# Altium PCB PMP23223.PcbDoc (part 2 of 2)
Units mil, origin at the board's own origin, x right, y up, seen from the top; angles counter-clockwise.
Board outline 2732.07 x 1574.8 mil, 4 copper layers (Top Layer 1, GND plane, Bottom Layer, Bottom Layer 1), stack 70.356 mil thick; 100 components, 33 nets, 239 pads, 115 vias.
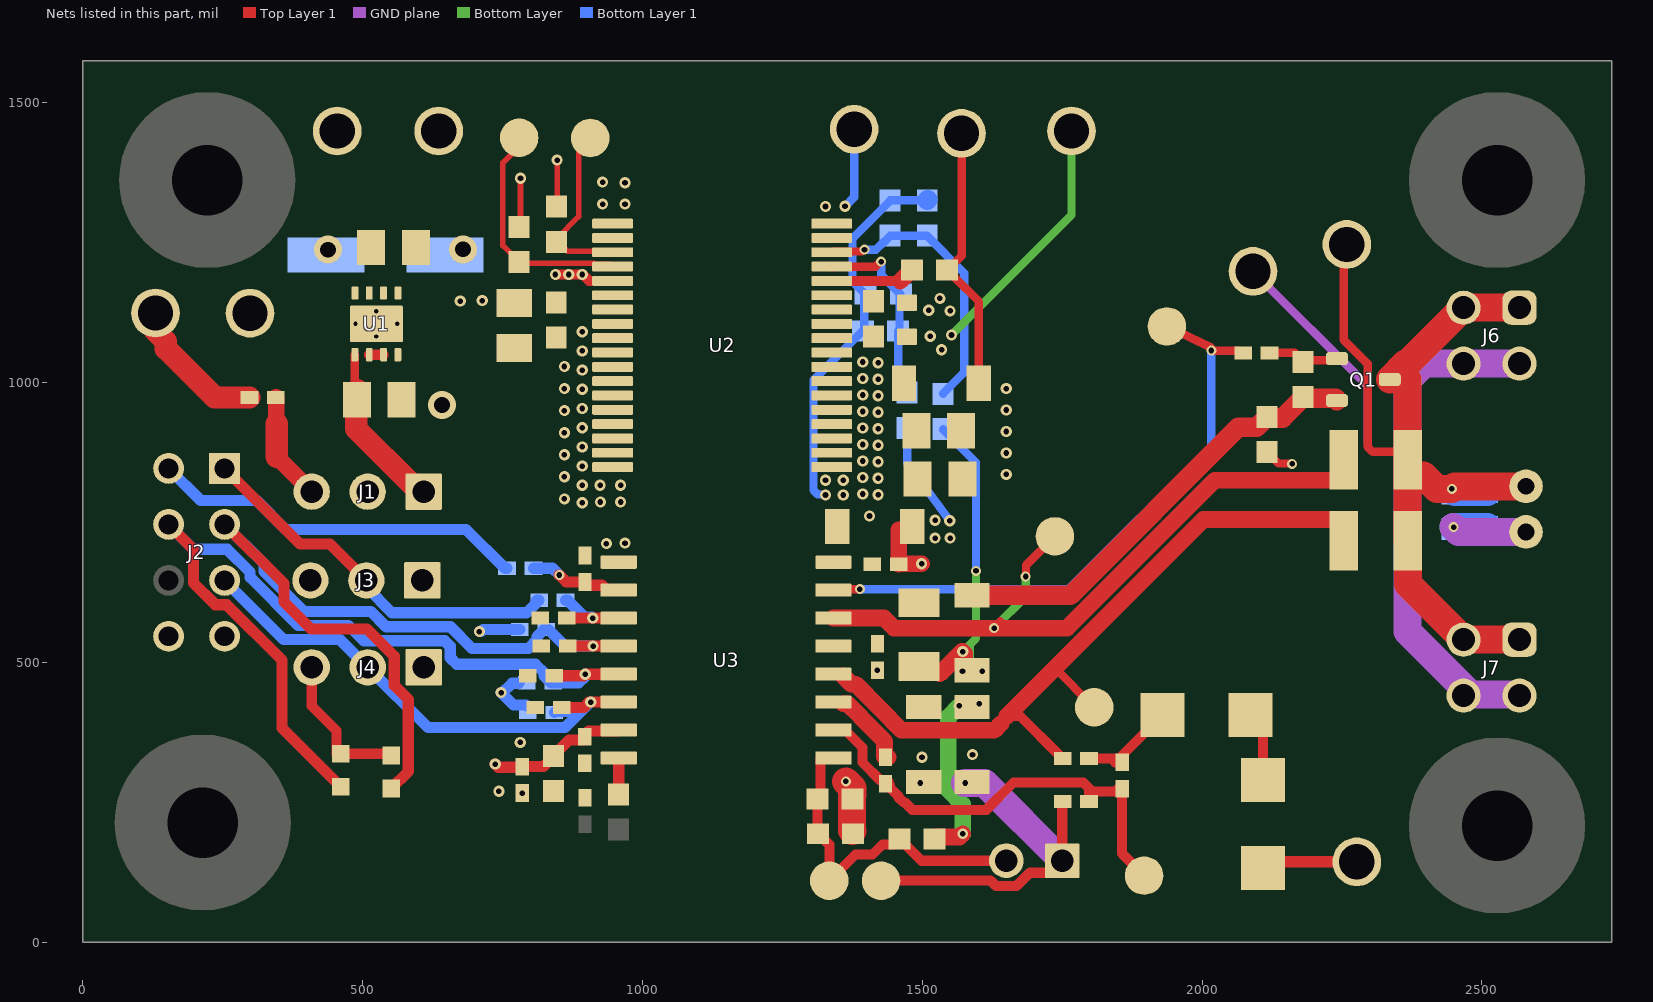
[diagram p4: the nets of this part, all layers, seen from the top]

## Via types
v1: diameter 20, hole 10, Top Layer 1 to Bottom Layer 1, tented top, 54 vias
v2: diameter 20, hole 10, Top Layer 1 to Bottom Layer 1, 41 vias
v3: diameter 18, hole 10, Top Layer 1 to Bottom Layer 1, tented both sides, 9 vias
v4: diameter 18, hole 10, Top Layer 1 to Bottom Layer 1, 4 vias
v5: diameter 19.68, hole 7.87, Top Layer 1 to Bottom Layer 1, 4 vias
v6: diameter 50, hole 28, Top Layer 1 to Bottom Layer 1, 3 vias

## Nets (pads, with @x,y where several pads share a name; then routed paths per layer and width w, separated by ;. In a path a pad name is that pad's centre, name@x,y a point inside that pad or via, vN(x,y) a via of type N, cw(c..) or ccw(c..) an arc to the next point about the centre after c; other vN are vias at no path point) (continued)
COM: C10.2 C11.2 C14.1 C15.1 C16.2 C19.2 C25.2 C27.2 C28.1 C29.1 C30.1 C32.2 J5.1 J6.2 J6.4 J7.2 J7.4 pad.2 R2.1 R3.2 R20.1 R28.2 R40.1 TP4.1 TP10.1 TP15.1 U3.3 | length 3283.5
  Top Layer 1 w15: R2.1@1544.22,1201.36 R2.1@1545.2,1201.36 ; TP4.1@1570.09,1445.54 1570.09,1226.25 R2.1@1545.2,1201.36 ; C15.1@1600.96,999.06 1600.96,1144.63 1556.41,1189.18 1556.41,1190.16 R2.1@1545.2,1201.36 ; TP10.1@2086.28,1198.13 2090.06,1198.13 TP10.1@2090.87,1198.94 ; C32.2@2116.2,876.95 C32.2@2116.2,875.96 2116.2,874.98 2127.4,863.78 2128.38,863.78 2136.62,855.54 2160.3,855.54 v3(2160.87,854.96)
  Top Layer 1 w18: TP15.1@1417.4,110.01 TP15.1@1426.18,110.01 1622.07,110.01 1631.38,100.71 1668.58,100.71 1692.07,124.21 1728.57,124.21 J5.1@1749.98,145.62 R28.2@1749.98,250.67 ; 1457.8,737.12 C28.1@1472.5,751.82 ; C28.1@1475.03,749.91 C28.1@1475.03,759.75
  Top Layer 1 w30: U3.3@1358.62,425.99 1366.65,425.99 1388.4,404.24 1388.4,403.67 1408.22,383.86 1408.22,383.47 1432.51,359.18 1432.51,331.39 1432.6,331.29 1435.84,331.29 1436.59,330.55 C25.2@1439.03,330.55 ; C14.1@1457.75,675.29 1457.75,675.54 1458.5,676.29 v2(1498.56,676.29) ; C14.1@1457.8,685.15 1457.8,737.12
  Top Layer 1 w50: v4(1363.39,287.37) 1375.43,275.33 1375.43,262.94 1374.35,261.86 1374.35,199.61 R40.1@1375.43,198.53
  GND plane w15: TP4.1@1570.09,1445.54 TP4.1@1574.6,1441.02 ; TP10.1@2090.87,1198.94 2295.9,993.91 2295.9,893.49
  GND plane w50: v2(1576.4,284.58) 1611.02,284.58 J5.1@1749.98,145.62 ; v3(2449.47,741.72) 2457.93,733.26 pad.2@2578.74,733.26 ; J7.2@2567.13,440.63 2565.02,442.74 2479.45,442.74 2367.21,554.98 2367.21,1004.6 2396.5,1033.88 J6.4@2467.13,1033.88 J6.2@2567.13,1033.88
  Bottom Layer 1 w15: R3.2@1472.89,918.96 1472.89,856.2 v1(1548.92,753.05) ; TP4.1@1569.85,1439.31 1570.09,1439.55 TP4.1@1570.09,1445.54
  Bottom Layer 1 w50: v3(2449.47,741.72) R20.1@2509.84,741.72
  other v1: 1522.84,722.13 1549.61,722.13 1522.7,754.04 1649.95,835.96 1649.95,874.32 1649.95,912.68 1649.95,951.04 1649.95,989.4
  other v2: 1496.21,284.58 1499.33,330.55 1589.52,335.3 1419.72,486.14
Drain: D4.1 TP14.1 | length 172
  Top Layer 1 w20: D4.1@2108.99,132.66 2119.97,143.65 TP14.1@2276.41,143.65
FLT: C23.1 D2.1 J2.4 R16.1 U3.13 | length 1605.9
  Top Layer 1 w20: J2.4@153.09,746.63 197.63,702.08 197.63,641.89 236.45,603.08 256.83,603.08 355.93,503.97 355.93,382.65 D2.1@455.04,283.55 ; C23.1@844.07,477.81 846.47,477.81 848.14,476.14 894.89,476.14 v2(897.53,478.78) 956.87,478.78 U3.13@957.28,479.18
  Bottom Layer 1 w20: J2.4@153.09,746.63 197.63,702.08 257.82,702.08 298.31,661.59 298.31,652.3 384.38,566.23 474.61,566.23 502.13,538.71 646.42,538.71 656.35,528.78 656.35,508.35 668.06,496.64 808.73,496.64 823.77,481.6 823.77,476.14 836.32,463.58 R16.1@840.26,463.58 885.81,463.58 897.53,475.29 v2(897.53,478.78)
GATE: C19.1 J6.1 J6.3 J7.1 J7.3 pad.3 Q1.3 R11.2 R14.2 R20.2 TP9.1 | length 1642.2
  Top Layer 1 w15: TP9.1@2253.03,1239.89 2253.03,1076.37 2295.9,1033.5 2295.9,885.09 2304.69,876.3 2353.33,876.3 R11.2@2367.21,862.43 ; Q1.3@2329.58,999.82 Q1.3@2335.27,1005.51
  Top Layer 1 w50: Q1.3@2335.27,1005.51 2363.72,1033.96 2367.21,1033.96 J6.3@2467.13,1133.88 J6.1@2567.13,1133.88 ; 2367.21,1005.51 R11.2@2367.21,862.43 R11.2@2367.21,834.87 ; J7.1@2567.13,540.63 J7.3@2467.13,540.63 2367.8,639.96 2367.8,717.21 R14.2@2367.21,717.8 R11.2@2367.21,834.87 ; pad.3@2578.74,814.7 2450.95,814.7 v3(2446.26,810.01) 2419.63,810.01 2395.36,834.28 2367.8,834.28 R11.2@2367.21,834.87
  Bottom Layer 1 w50: v3(2446.26,810.01) 2451.55,804.71 R20.2@2509.84,804.71
GND: C1.2 C2.2 C6.2 C7.2 C17.1 C18.2 C20.2 C21.2 C22.2 C23.2 C24.2 C26.2 C31.2 D2.2 D3.2 J2.7 J2.8 J3.3 J4.3 R10.1 TP2.1 TP20.1 U1.2 U1.3 U1.4 U1.5 U1.6 U1.9 U2.1 U2.2 U2.5 U2.8 U2.9 U2.10 U2.11 U2.12 U2.13 U2.14 U2.15 U2.16 U2.17 U2.18 U3.9 | length 402.9
  Top Layer 1 w18: J4.3@408.78,500.07 408.78,422.17 452.91,378.04 D2.2@452.91,334.89 ; D2.2@460.79,336.85 D3.2@547.3,336.85 ; U1.2@511.58,1049.87 U1.3@537.17,1049.87 ; v2(844.21,1193.15) v2(868.22,1193.15) v2(892.32,1193.15) ; v2@892.32,1194.15 904.57,1181.9 946.31,1181.9 U2.5@946.45,1181.76
  other v1: 892.32,785.36 924.64,786.61 960.72,786.61 860.34,792.22 892.32,816.57 924.09,816.57 960.72,816.57 860.34,831.66 892.32,850.88 860.34,871.1 892.32,885.19 860.34,910.53 892.32,919.5 860.34,949.97 892.32,953.8 892.32,988.11 860.34,989.4 892.32,1022.42 860.34,1028.84 892.32,1056.73 892.32,1091.04
  other v2: 785.18,266.58 743.25,269.93 781.48,357.13 935.42,712.27 968.68,713.24 928.62,1318.97 968.68,1318.97 968.68,1357.09 928.62,1358.4
  other v5: 524.38,1082.35 486.98,1104.99 561.78,1104.99 524.38,1127.62
  other v6: 641.48,960.01 679.25,1238.11
IN+: J2.2 R22.2 | length 678.6
  Bottom Layer 1 w20: J2.2@153.09,846.63 210.53,789.19 310.53,789.19 361.96,737.75 684.45,737.75 753.92,668.28 R22.2@757.86,668.28
IN-: J2.1 J3.2 R23.2 | length 687.5
  Top Layer 1 w20: J2.1@253.09,846.63 388.09,711.63 441.48,711.63 J3.2@506.48,646.63
  Bottom Layer 1 w20: J3.2@506.48,646.63 506.48,634.46 552.24,588.71 792.63,588.71 809.32,605.4 809.32,609.33 811.13,611.14 R23.2@815.07,611.14
NetC2_1: C2.1 J1.1 U1.1 | length 300.6
  Top Layer 1 w15: C2.1@485.99,986.43 U1.1@485.99,1049.87
  Top Layer 1 w40: C2.1@489.99,986.43 488.38,984.82 488.38,917.28 588.11,817.55 596.74,817.55 J1.1@609.22,805.07
NetC8_1: C8.1 R3.1 R7.2 U2.33 | length 349.9
  Top Layer 1 w15: U2.33@1339.3,1206.23 U2.33@1338.18,1207.35 1416.51,1207.35 1425.37,1216.21 v3(1426.18,1216.21)
  Bottom Layer 1 w15: v3(1426.18,1216.21) 1426.75,1215.63 1426.75,1191.93 1460.47,1158.21 1459.11,1156.85 1459.11,1094.6 R7.2@1456.77,1092.26 1456.77,999.06 1472.89,982.94 R3.1@1472.89,981.96
NetC9_1: C9.1 R4.1 R8.2 U2.34 | length 509
  Top Layer 1 w15: U2.34@1338.18,1232.94 1339.54,1234.3 1392.44,1234.3 1395.84,1237.7 v3(1396.65,1237.7)
  Bottom Layer 1 w15: v3(1396.65,1237.7) 1417.17,1237.7 1430.03,1250.56 1431.01,1250.56 1442.22,1261.76 C9.1@1442.22,1262.74 R8.2@1508.68,1262.75 1508.68,1261.76 1574.6,1195.83 1574.6,1018.32 1537.22,980.93 R4.1@1537.22,979.95
NetC20_1: C20.1 R22.1 U3.10 | length 170.7
  Top Layer 1 w20: v4(851.25,656.29) 863.76,643.78 C20.1@897.16,643.78 897.16,639.84 898.97,638.03 927.76,638.03 936.61,629.18 U3.10@957.28,629.18
  Bottom Layer 1 w20: R22.1@805.1,668.28 839.26,668.28 v4(851.25,656.29)
NetC21_1: C21.1 R23.1 U3.11 | length 154.5
  Top Layer 1 w20: C21.1@864.64,579.18 v2(910.96,579.18) U3.11@957.28,579.18
  Bottom Layer 1 w20: R23.1@862.31,611.14 866.25,611.14 896.3,581.1 909.05,581.1 v2(910.96,579.18)
NetC25_1: C25.1 R13.2 R28.1 TP13.1 U3.2 | length 813.2
  Top Layer 1 w18: U3.2@1341.13,379.18 1361.8,379.18 1393.02,347.97 1393.02,321.01 1423.89,290.14 1436.13,290.14 1439.03,287.24 1439.03,283.3 1441.84,280.49 1441.84,276.55 1457.11,261.29 1457.11,259.09 1465.31,250.89 1467.51,250.89 1481.77,236.62 1614.32,236.62 1663.06,285.36 1787.62,285.36 1798.17,274.82 1798.17,272.55 ; R28.1@1796.49,251.33 1798.17,272.55 ; R13.2@1848.63,273.39 1848.63,272.27 1845.82,269.46 1798.17,269.46 1798.17,272.55 ; R13.2@1857.07,274.32 1857.07,158.21 TP13.1@1896.19,119.08
NetD1_1: D1.1 D4.2 | length 125.2
  Top Layer 1 w18: D1.1@2086.56,406.02 2108.99,383.59 D4.2@2108.99,290.14
NetD1_2: D1.2 R1.2 R13.1 | length 195.7
  Top Layer 1 w18: R1.2@1797.78,328.31 R13.1@1851.38,328.31 ; R13.1@1857.07,321.56 R13.1@1855.78,321.56 ; D1.2@1929.08,406.02 R13.1@1851.38,328.31 ; R13.1@1851.38,328.31 1844.63,321.56 R13.1@1855.78,321.56 ; R13.1@1851.38,328.31 1854.26,328.31 1855.78,326.79 R13.1@1855.78,321.56
NetJ1_3: J1.3 R9.2 | length 195
  Top Layer 1 w30: R9.2@344.76,973.52 345.51,972.77 345.51,927.1 346.35,926.25 ; 346.35,867.49 J1.3@408.78,805.07
  Top Layer 1 w40: 346.35,867.49 346.35,926.25
NetQ1_1: Q1.1 R25.1 R26.2 | length 132.5
  Top Layer 1 w15: R25.1@2123.02,1050.45 R25.1@2120.37,1053.1 2165.11,1053.1 2180.22,1037.99 2182.19,1039.96 2237.83,1039.96 Q1.1@2240.78,1042.91
NetR1_1: R1.1 R14.1 TP11.1 U3.4 | length 1357.4
  Top Layer 1 w15: 1640.31,390.47 1654.09,404.24 ; 1736.91,489.83 TP11.1@1807.03,419.7
  Top Layer 1 w18: 1651.32,404.24 1654.09,404.24 1674.61,404.24 1743.79,335.06 1743.79,331.12 1746.6,328.31 R1.1@1750.54,328.31
  Top Layer 1 w30: U3.4@1358.62,475.99 1373.62,460.99 1381.15,460.99 1423.4,418.74 1423.4,418.17 1462.82,378.75 1628.6,378.75 1640.31,390.47 ; 1651.32,404.24 1736.91,489.83 2002.54,755.45 2242.44,755.45 2253.03,744.86 R14.1@2253.03,717.8
NetR2_2: R2.2 U2.32 | length 151.2
  Top Layer 1 w18: U2.32@1338.18,1181.76 1460.64,1181.76
  Top Layer 1 w30: 1460.64,1181.76 1480.24,1201.36 R2.2@1481.23,1201.36
NetR5_1: R5.1 TP6.1 U2.4 | length 411
  Top Layer 1 w10: R5.1@779.12,1215.26 R5.1@779.12,1216.24 ; R5.1@785.11,1210.24 R5.1@779.12,1216.24 ; TP6.1@787.35,1429.81 750.42,1392.88 750.42,1244.94 R5.1@779.12,1216.24 ; R5.1@788.92,1209.26 792.82,1213.15 913.09,1213.15 915.03,1211.21 944.5,1211.21 U2.4@946.45,1209.26
NetR6_2: R6.2 TP5.1 U2.3 | length 339.2
  Top Layer 1 w10: TP5.1@915.03,1445.54 885.65,1416.15 885.65,1296.67 845.94,1256.96 845.94,1255.98 845.94,1254.99 866.08,1234.85 U2.3@946.45,1234.85 ; TP5.1@915.67,1446.17 TP5.1@915.67,1457.33
NetR9_1: R9.1 TP17.1 | length 239.9
  Top Layer 1 w40: TP17.1@127.95,1106.9 127.95,1094.18 148.25,1073.88 148.25,1060.82 235.55,973.52 R9.1@297.52,973.52
NetR11_1: R11.1 TP8.1 U3.6 | length 1286.3
  Top Layer 1 w15: 1638.86,573.67 1651.36,561.18 ; v3(1684.68,653.63) 1685.25,654.21 1685.25,673.6 TP8.1@1736.91,725.25
  Top Layer 1 w30: U3.6@1341.13,579.18 1431.39,579.18 1449.4,561.18 v3(1628.19,561.18) 1651.36,561.18 1758.76,561.18 2023.17,825.58 2242.44,825.58 2253.03,836.17 R11.1@2253.03,862.43
  Bottom Layer w15: v3(1628.19,561.18) 1684.68,617.67 v3(1684.68,653.63)
NetR25_2: R25.2 TP12.1 U3.7 | length 1100.6
  Top Layer 1 w15: U3.7@1341.13,629.18 1343.02,631.07 v4(1388.4,631.07) ; TP12.1@1937.08,1100.43 2015.8,1062.87 2015.8,1057.98 v3(2016.38,1057.41) 2016.95,1056.83 2065.45,1056.83 R25.2@2069.19,1053.1
  Bottom Layer 1 w15: v4(1388.4,631.07) 1761.55,631.07 2016.38,885.9 v3(2016.38,1057.41)
NetR31_1: R31.1 U3.16 | length 65.2
  Top Layer 1 w20: R31.1@957.28,264.03 U3.16@957.28,329.18
RDY: C22.1 D3.1 J2.3 R15.1 U3.12 | length 1558.3
  Top Layer 1 w20: J2.3@253.09,746.63 359,640.71 359,608.24 407.67,559.57 507.67,559.57 556.35,510.89 556.35,458.71 581.34,433.72 581.34,305.41 D3.1@550.59,274.66 ; C22.1@866.02,529.18 v2(911.65,529.18) U3.12@957.28,529.18
  Bottom Layer 1 w20: J2.3@253.09,746.63 323.31,676.4 323.31,662.65 394.74,591.23 514.36,591.23 541.88,563.71 656.77,563.71 695.48,525 795.88,525 811.54,540.66 811.54,546.12 824.09,558.68 R15.1@828.03,558.68 831.97,558.68 861.47,529.18 v2(911.65,529.18)
RST/EN: C24.1 J2.5 J4.2 R17.1 U3.14 | length 933.7
  Top Layer 1 w20: C24.1@855.6,419.7 895.13,419.7 904.61,429.18 v2(907.32,429.18) U3.14@957.28,429.18
  Bottom Layer 1 w20: J2.5@253.09,646.63 358.49,541.23 458.87,541.23 J4.2@508.87,491.23 616.62,383.47 861.61,383.47 v2(907.32,429.18) ; R17.1@842.4,410.29 844.21,412.1 887.53,412.1
TR+: C27.1 J5.2 R18.1 R40.2 TP16.1 U3.1 | length 611.2
  Top Layer 1 w18: R40.2@1311.45,198.53 1312.44,199.51 C27.1@1312.44,256.15 1312.44,262.94 1317.65,268.16 1317.65,326.37 1320.47,329.18 U3.1@1341.13,329.18 ; R40.2@1313.2,193.86 1314.18,193.86 1333.73,174.3 TP16.1@1333.73,110.01 1380.63,156.91 1411.01,156.91 1428.93,174.83 1449.03,174.83 R18.1@1458.73,184.53 1459.71,184.53 1498.63,145.62 J5.2@1649.98,145.62
VBIAS: C17.2 C18.1 J1.2 J3.1 J4.1 R5.2 R6.1 R10.2 R15.2 R16.2 R17.2 U3.15 | length 595.9
  Top Layer 1 w10: R5.2@779.12,1278.25 781.84,1280.97 v2(781.84,1365.07) ; R6.1@845.94,1314.67 847.37,1316.09 v2(847.37,1397.64)
  Top Layer 1 w20: v2(736.64,318.35) 742.15,312.84 783.36,312.84 784.34,313.82 822.9,313.82 841.02,331.94 C17.2@841.02,332.92 841.02,333.91 868.33,361.22 894.97,361.22 896.78,363.03 C18.1@896.78,366.97 896.78,370.91 903.25,377.37 955.47,377.37 U3.15@957.28,379.18
  Bottom Layer 1 w20: v1(708.43,555) 711.14,555 714.82,558.68 R15.2@780.79,558.68 ; R16.2@778.67,462.64 766.45,462.64 749.87,446.07 v2(747.17,446.07) 769.32,423.91 791.37,423.91 793.18,422.1
VDD: C3.1 C4.2 C10.1 C11.1 C12.1 C13.1 C16.1 R4.2 R18.2 TP3.1 U2.28 U2.29 U3.5 | length 1345.7
  Top Layer 1 w30: C16.1@1499.33,417.13 C16.1@1502.61,420.4 C16.1@1506.22,416.78 ; R18.2@1521.72,184.53 1525.42,188.23 1566.48,188.23 v4(1572.1,193.86) ; 1531.21,479.75 1570.83,519.38 v2(1572.1,519.38) 1575.52,515.97 C13.1@1575.52,492.67 ; C11.1@1598.12,422.74 v2(1601.4,426.02)
  Bottom Layer w15: v2(1552.1,1085.14) 1766.55,1299.59 TP3.1@1766.55,1449.65 ; v2(1571.64,484.28) 1572.59,485.23 1582.64,485.23 1585.06,487.65 1585.06,532.33 ; v2(1572.1,519.38) 1585.06,532.33 ; v3(1595.76,663.47) 1595.76,543.04 1585.06,532.33
  Bottom Layer w30: v2(1565.87,422.37) 1546.4,402.9 1546.4,272.15 1572.1,246.44 v4(1572.1,193.86)
  Bottom Layer 1 w15: R4.2@1537.22,916.96 1537.22,915.97 1595.76,857.43 v3(1595.76,663.47)
  other v2: 1607.09,484.55 1534.38,1058.61 1514.13,1082.76
VEE: C3.2 C4.1 C8.2 C9.2 C12.2 C13.2 C14.2 C15.2 C28.2 C29.2 C30.2 C32.1 Q1.2 R7.1 R8.1 R26.1 TP7.1 U2.19 U2.20 U2.21 U2.22 U2.23 U2.24 U2.25 U2.26 U2.27 U2.30 U2.31 U2.35 U2.36 U3.8 | length 1634.4
  Top Layer 1 w35: C13.2@1588.82,619.87 1764.43,619.87 2064.98,920.43 2097.67,920.43 2114.01,936.77 2143.97,936.77 2180.22,973.03 R26.1@2180.22,974.01 ; R26.1@2180.22,971.83 2238.6,971.83 2240.78,969.64 Q1.2@2240.78,968.1
  Bottom Layer 1 w15: v1(1326.85,799.13) 1325.89,800.09 1313.12,800.09 1305.46,807.74 1305.46,1004.93 1392.79,1092.26 R7.1@1393.78,1092.26 1396.12,1094.6 1396.12,1155.87 C8.2@1398.46,1158.21 1397.48,1158.21 1375.15,1180.53 1375.15,1257.69 1442.22,1324.75 C9.2@1442.22,1325.74 R8.1@1508.68,1325.74 ; v2(1361.8,1315.04) 1378.21,1331.45 TP7.1@1378.21,1452.76
  Bottom Layer 1 w35: R8.1@1508.68,1325.74 R8.1@1509.88,1326.94
  other v1: 1405.57,761.66 1358.62,799.13 1420.9,799.53 1393.5,801.04 1326.85,825.58 1358.62,825.58 1420.9,829.01 1393.5,830.52 1420.9,858.5 1393.5,860.01 1420.9,887.98 1393.5,889.49 1420.9,917.46 1393.5,918.97 1420.9,946.94 1393.5,948.45 1420.9,976.43 1393.5,977.94 1420.9,1005.91 1393.5,1007.42 1420.9,1035.39 1393.5,1036.9
  other v2: 1549.61,1128.1 1511.37,1129.37 1531.43,1150.53 1326.85,1314.67
VIN: C1.1 C6.1 C7.1 C31.1 TP1.1 U1.7 U1.8 U2.6 U2.7
  other v2: 674.18,1145.65 713.59,1146.55
  other v6: 437.83,1237.7
pads on no net: H1.0 H2.0 H3.0 H4.1 H5.0 H6.1 H7.1 H8.1

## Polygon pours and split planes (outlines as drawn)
VEE on Bottom Layer 1 "BOTTOM_LAYER_1_VEE_P045" (solid, remove dead copper, pour order 45): 1288.21,1382.8 1290.49,1385.08 1601.12,1385.08 1601.12,150.94 1595.42,145.24 1573.33,167.32 1296.64,167.32 1296.64,1385.28 1299.48,1388.13
IN+ on Bottom Layer 1 "BOTTOM_LAYER_1_IN+_P044" (solid, remove dead copper, pour order 44): 0,1574.8 988.63,1574.8 986.58,1572.76 986.58,2.04 7.96,2.04 0,10
VIN on Bottom Layer 1 "BOTTOM_LAYER_1_VIN_P006" (solid, pour order 6): 553.97,1524.37 368.36,1524.37 368.36,1187.93 410.71,1145.58 549.25,1145.58 601.61,1093.22 756.89,1093.22 756.89,1183.67 578.89,1183.67 554.98,1212.82 554.98,1337.28 554.98,1212.82
GND on Bottom Layer 1 "BOTTOM_LAYER_1_GND_P007" (solid, pour order 7): 735.43,1525.59 575.27,1525.59 574.05,1524.37 578.89,1519.53 578.89,1197.28 725.83,1197.28 735.43,1206.88
GND on Top Layer 1 "TOP_LAYER_1_GND_P043" (solid, remove dead copper, pour order 43): -5,1574.8 -2.96,1572.76 986.58,1572.76 986.58,2.04 983.75,-0.79 979.8,3.16 0,3.16
COM on Top Layer 1 "TOP_LAYER_1_COM_P042" (solid, pour order 42): 1516.57,1040.33 1663.06,1040.33 1663.06,812.04 1556.26,705.25 1447.91,705.25 1447.91,783.99 1452.23,779.67 1520.6,779.67
VEE on Top Layer 1 "TOP_LAYER_1_VEE_P026" (solid, pour order 26): 1292.07,1169.68 1292.07,1115.17 1296.61,1110.63 1570.83,1110.63 1570.83,1166.48 1374.74,1166.48
VDD on Top Layer 1 "TOP_LAYER_1_VDD_P029" (solid, pour order 29): 1296.92,1121.73 1295.02,1119.83 1295.02,1040.33 1539.63,1040.33 1571.64,1072.33 1571.64,1100.96
VEE on Top Layer 1 "TOP_LAYER_1_VEE_P024" (solid, pour order 24): 1291.92,1066.6 1298.12,1060.4 1518.72,1060.4 1518.72,748.04 1434.18,663.49 1440.39,657.28 1585.06,657.28 1585.06,567.37 1571.33,581.1 1404.65,581.1 1404.65,652.69 1386.18,652.69 1296.46,652.69
VEE on Top Layer 1 "TOP_LAYER_1_VEE_P027" (solid, pour order 27): 1303.24,1244.94 1299.05,1249.13 1299.05,1329.17 1420.9,1329.17 1420.9,1259.32
GND on Top Layer 1 "TOP_LAYER_1_GND_P016" (solid, pour order 16): 992.71,666.52 991.38,665.19 669.49,665.19 669.49,924.85 537.69,924.85 515.58,946.95 515.58,1051.34 231.85,1051.34 226.38,1056.81 226.38,1177.25 519.73,1177.25 528.64,1168.34 534.29,1173.99 534.29,1301.41 713.59,1301.41 714.85,1302.67 714.85,1204 616.62,1204 613.02,1200.4 620.5,1192.92 620.5,1116.74 984.54,1125.22 992.71,1117.06
VIN on Top Layer 1 "TOP_LAYER_1_VIN_P010" (solid, pour order 10): 480.28,1165.82 479.89,1145.58 520.43,1147.47 521.29,1165.57 524.44,1168.72 524.44,1201.36 529.72,1201.36 541.18,1212.82 541.18,1281.36 406.47,1281.36 406.47,1202.76 479.58,1202.76 480.98,1201.36
VIN on Top Layer 1 "TOP_LAYER_1_VIN_P019" (solid, pour order 19): 984.54,1174.28 984.54,1115.38 643.97,1115.38 643.97,1173.48
COM on Top Layer 1 "TOP_LAYER_1_COM_P035" (solid, pour order 35): 1308.29,410.64 1308.29,451.04 1396.65,451.04 1494.54,353.15 1628.19,353.15 1628.19,252.08 1620.77,259.5 1470.59,259.5 1470.59,297.02 1446.91,320.7 1423.07,323.08 1376.49,410.64 1335.51,410.64
GND on Top Layer 1 "TOP_LAYER_1_GND_P023" (solid, pour order 23): 841.02,600.84 841.02,389.76 789.45,338.2 765.01,338.2 765.01,599.86 764.03,600.84
VDD on Top Layer 1 "TOP_LAYER_1_VDD_P032" (solid, pour order 32): 1296.46,558.68 1305.46,549.68 1640.31,549.68 1640.31,401.03 1628.19,388.91 1625.96,391.14 1465.2,391.14 1465.2,410.15 1371.01,504.35 1296.46,504.35
GND on Top Layer 1 "TOP_LAYER_1_GND_P022" (solid, pour order 22): 918.43,343.35 918.81,342.97 918.81,234.5 726.59,234.5 722.04,239.05 725,242.01 725,292.51
GND on Top Layer 1 "TOP_LAYER_1_GND_P014" (solid, pour order 14): 992.71,1248.26 997.63,1253.18 997.63,1376.9 873.2,1376.9 873.2,1240.48
GND on Top Layer 1 "TOP_LAYER_1_GND_P013" (solid, pour order 13): 532.03,1162.08 531.55,1161.6 229.9,1161.6 226.38,1158.08 226.38,1046.97 454.22,1046.97 467.36,1060.11 467.36,1094.19 551.91,1094.19 553.18,1092.92 553.18,1152.37
VEE on GND plane "GND_PLANE_VEE_P028" (solid, pour order 28): 1498.84,1172.82 1505.19,1166.48 1570.83,1166.48 1570.83,1115.19 1558.69,1103.05 1498.84,1103.05 1498.84,709.26 1311.04,709.26 1294.2,726.11 1295.02,1340.07 1512.17,1340.07 1498.84,1326.74
COM on GND plane "GND_PLANE_COM_P036" (solid, pour order 36): 1856.46,580.15 1857.07,579.55 1857.07,276.29 1641.67,276.29 1635.31,269.93 1316.48,269.93 1309.48,262.94 1296.46,275.96 1296.46,636.6 1426.18,636.6 1498.34,708.76 1498.34,756.71 1548.13,806.49 1548.13,1038.43 1633,1038.43 1792.79,878.64 2009.13,878.64 2009.13,890.98 2039.08,920.93 2381.14,920.93 2381.14,802.29 2419.05,764.38 2538.39,764.38 2538.39,702.13 2401.32,702.13 2401.32,656.07 2393.92,663.47 2217.6,663.47 2217.6,733.26 2217.4,733.46 2009.77,733.46
GND on GND plane "GND_PLANE_GND_P000" (solid, remove dead copper, pour order 0): 0,1574.8 984.25,1574.8 984.25,0.29 984.54,0 982.96,-1.58 -4.74,-1.58
VEE on Bottom Layer "BOTTOM_LAYER_VEE_P046" (solid, remove dead copper, pour order 46): 1308.29,1340.07 1312.44,1335.92 1578.2,1335.92 1578.2,127.95 1549.87,156.28 1305.46,156.28
VDD on Bottom Layer "BOTTOM_LAYER_VDD_P033" (solid, pour order 33): 1457.45,1102.64 1463.41,1096.68 1563.28,1096.68 1563.28,589.9 1628.19,525 1626.22,523.03 1626.22,378.75 1462.82,378.75 1454.98,386.6
VBIAS on Bottom Layer "BOTTOM_LAYER_VBIAS_P021" (solid, remove dead copper, pour order 21): 988.63,1574.8 984.54,1570.72 984.54,0 -3.16,0 0,3.16 0,1574.8

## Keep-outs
Keep-Out Layer:
  lines w10: 2731.38,9.84 2731.38,1579.8 0,1579.8 ; 2732.07,-5 0,-5 ; -5,0 ccw(c0,0) 0,-5 ; -5,0 ccw(c0,0) 0,-5 ; -5,0 -5,1574.8 ; -5,1574.8 cw(c0,1574.8) 0,1579.8 ; -5,1574.8 cw(c0,1574.8) 0,1579.8
  text ".Layer_Name" at 577,-858.49 h60

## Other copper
Top Layer 1:
  text ".Layer_Name" at 577,-858.49 h60
Bottom Layer 1:
  text ".Layer_Name" at 577,-858.49 h60

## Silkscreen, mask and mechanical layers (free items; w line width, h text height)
Top Overlay:
  lines w10: 86.79,629.18 115.14,629.18 ; 87.87,765.92 113.29,765.92 ; 150.25,484.08 150.25,506.96 ; 153.09,889.13 153.09,907.52 ; 243.36,915.54 243.36,895.04 244.89,893.52 ; 253.09,485.63 253.09,504.12 ; 288.09,761.13 313.41,761.13 ; 291.76,652.69 313.41,652.69
  text "ENA" at 741.48,1490.5 h30
  text "PG" at 888.27,1481.54 h30
  text "VEE" at 1291.05,1416.97 h30 r90
  text "+VIN-" at 472.76,1346.54 h30
  text "VDD" at 1728.84,1334.97 h30
  text "COM" at 1535.47,1330.75 h30
  text "GATE" at 2185.89,1330.61 h30
  text "SOURCE" at 1843.41,1175.7 h30
  text "GATE" at 2284.41,1123.19 h30
  text "CLMPE" at 1759.2,1037.07 h30
  text "+VBias 5V-" at 58.43,1010.81 h30
  text "SOURCE" at 2447.76,944.61 h30
  text "IN-" at 215.37,923.54 h30
  text "IN+" at 113.97,921.51 h30
  text "EXT<VBIAS>LDO" at 361.95,871.94 h30
  text "GATE" at 2540.99,863.93 h30
  text "RDY" at 318.53,798.2 h30 r270
  text "OUTL" at 1671.06,781.51 h30
  text "FLT" at 74.57,733.25 h30 r90
  text "GND<IN->VBias" at 361.95,709.1 h30
  text "RST/EN" at 306.04,693.67 h30 r270
  text "SOURCE" at 2501.7,660.55 h30
  text "APWM" at 79.87,580.1 h30 r90
  text "GND<RST/EN>5V" at 358,557.18 h30
  text "GATE" at 2284.41,533 h30
  text "GND" at 92.09,442.74 h30
  text "GND" at 211.09,441.72 h30
  text "SOURCE" at 2227.72,420.53 h30
  text "OUTH" at 1642.25,402.97 h30
  text "FLT" at 428.03,279.91 h30 r90
  text "RDY" at 521.36,270.03 h30 r90
  text "DRAIN" at 2202.88,229.06 h30
  text "OC" at 1949.52,83.33 h30
  text "TR+,COM" at 1603.76,57.37 h30
  text "'.PRJ_Number'.PCB_Rev" at 400.88,55.17 h108.27
  text "AIN" at 1293.57,27.68 h30
  text "COM" at 1412.65,27.68 h30
  text ".Layer_Name" at 577,-858.49 h60
Bottom Overlay:
  text ".Layer_Name" at 577,-858.49 h60
Top Paste:
  text ".Layer_Name" at 577,-858.49 h60
Bottom Paste:
  text ".Layer_Name" at 577,-858.49 h60
Top Solder:
  text ".Layer_Name" at 577,-858.49 h60
  text ".Layer_Name" at 577,-858.49 h60
Bottom Solder:
  text ".Layer_Name" at 577,-858.49 h60
Drill Guide:
  text ".Layer_Name" at 577,-858.49 h60
M1 Board Outline:
  the board outline again, w10
  text ".Layer_Name" at 577,-858.49 h60
M2 Board Dimensions:
  rectangle: 0,-275 125,-150
  rectangle: 125,-400 500,-275
  lines w7: 0,-275 1000,-275 ; 125,-400 125,-150 ; 250,-400 250,-150 ; 500,-400 500,-150 ; 750,-400 750,-150 ; 0,-400 1000,-400 1000,-150 0,-150 0,-400
  text ".Layer_Name" at 577,-858.49 h60
M3 3D STEP Top:
  text ".Layer_Name" at 577,-858.49 h60
M4 3D STEP Bottom:
  text ".Layer_Name" at 577,-858.49 h60
M5 Assembly Top:
  lines w10: -292,-930.17 6308,-930.17 ; -292,-726.83 6310,-726.83 ; -292,-523.5 -292,-1133.5 3713,-1133.5 6310,-1133.5 6310,-523.5 -291.5,-523.5 -291.5,-1133.5 1284,-1133.5 ; 2173,-1133.5 2173,-523.5 ; 3440,-726.83 3440,-523.5 ; 4280,-726.83 4280,-523.5 ; 4902,-1140 4902,-937.17
  text "COMPONENTS MARKED 'DNP' SHOULD NOT BE POPULATED." at 1153.5,-318.5 h60
  text "ASSEMBLY VARIANT:" at 1153,-434 h60
  text ".VariantName" at 2189,-434 h60
  text "PCB VIEWED FROM TOP SIDE" at -228.5,-655.67 h60
  text "BOARD #:" at 2248,-655.67 h60
  text ".PRJ_Number" at 2793.5,-655.67 h60
  text "REV:" at 3638,-655.67 h60
  text ".PCB_Rev" at 3929.5,-655.67 h60
  text "SVN REV:" at 4476,-655.67 h60
  text ".VersionControl_RevNumber" at 4982,-655.67 h60
  text "TID #:" at 2248,-859 h60
  text ".TID" at 2793.5,-859 h60
  text "PLOT NAME =" at -228.5,-1064.34 h60
  text ".plot_File_Name" at 577,-1064.34 h60
  text "GENERATED    :" at 2250,-1064.34 h60
  text ".Print_Date" at 3119.5,-1064.34 h60
  text ".Print_Time" at 3848.5,-1064.34 h60
  text "TEXAS INSTRUMENTS" at 5113,-1064.34 h60
M6 Assembly Bottom:
  lines w10: -292.5,-727.33 6309.5,-727.33 ; -290.5,-930.67 6309.5,-930.67 ; 1115.5,-1140.5 1115.5,-937.67 ; 1737.5,-727.33 1737.5,-524 ; 2577.5,-727.33 2577.5,-524 ; 3844.5,-1134 3844.5,-524 ; 4733.5,-1134 6309,-1134 6309,-524 -292.5,-524 -292.5,-1134 2304.5,-1134 6309.5,-1134 6309.5,-524
  text "COMPONENTS MARKED 'DNP' SHOULD NOT BE POPULATED." at 6102,-318 h60
  text ".VariantName" at 5058,-434 h60
  text "ASSEMBLY VARIANT:" at 6097,-434 h60
  text ".VersionControl_RevNumber" at 1035.5,-656.17 h60
  text "SVN REV:" at 1541.5,-656.17 h60
  text ".PCB_Rev" at 2088,-656.17 h60
  text "REV:" at 2379.5,-656.17 h60
  text ".PRJ_Number" at 3224,-656.17 h60
  text "BOARD #:" at 3769.5,-656.17 h60
  text "PCB VIEWED FROM BOTTOM SIDE" at 6246,-656.17 h60
  text ".TID" at 3224,-859.5 h60
  text "TID #:" at 3769.5,-859.5 h60
  text "TEXAS INSTRUMENTS" at 904.5,-1064.84 h60
  text ".Print_Time" at 2169,-1064.84 h60
  text ".Print_Date" at 2898,-1064.84 h60
  text "GENERATED    :" at 3767.5,-1064.84 h60
  text ".plot_File_Name" at 5440.5,-1064.84 h60
  text "PLOT NAME =" at 6246,-1064.84 h60
M9 Title Sheet:
  drawing of 57 lines, arcs and shapes, not listed
  text "1" at 739.84,8036.5 h70
  text "2" at 3235.5,8036.5 h70
  text "3" at 5724.84,8036.5 h70
  text "4" at 8231.51,8036.5 h70
  text "5" at 10730.5,8036.5 h70
  text "6" at 13235.5,8036.5 h70
  text "A" at -416.5,6893.5 h70
  text "A" at 14383.5,6893.5 h70
  text "B" at -416.5,4513.5 h70
  text "B" at 14383.5,4513.5 h70
  text "C" at -416.5,2138.5 h70
  text "C" at 14383.5,2138.5 h70
  text "PROJECT TITLE:" at 11343.5,277.5 h45
  text ".PRJ_Title" at 11393.5,144.17 h70
  text "DESIGNED FOR:" at 11343.5,-23.5 h45
  text ".PRJ_Customer" at 11393.5,-163.5 h70
  text "D" at -416.5,-231.5 h70
  text "D" at 14383.5,-231.5 h70
  text "FILE NAME:" at 11343.5,-323.5 h45
  text ".PCB_File_Name_No_Path" at 11393.5,-443.5 h70
  text "Texas Instruments (TI) and/or its licensors do not warrant the accuracy or completeness of this specification" at 6374,-605.34 h45
  text "ENGINEER:" at 11343.5,-613.5 h45
  text "LAYOUT BY:" at 12848.5,-613.5 h45
  text "or any information contained therein. TI and/or its licensors do not warrant that this design will meet" at 6329.01,-718 h45
  text ".PRJ_Engineer" at 11393.5,-768.49 h70
  text ".PCB_Layout" at 12899,-768.49 h70
  text "the specifications, will be suitable for your application or fit for any particular purpose, or will operate in" at 6329.01,-830.67 h45
  text ".Layer_Name" at 577,-858.49 h60
  text "ALTIUM DESIGNER VERSION:" at 12848.5,-923.5 h45
  text "an implementation. TI and/or its licensors do not warrant that the design is production worthy. You should" at 6329.01,-943.33 h45
  text "completely validate and test your design implementation to confirm the system functionality for your application." at 6374,-1056 h45
  text ".print_Scale" at 11393.5,-1056.83 h70
  text ".Application_BuildNumber" at 12899,-1056.83 h70
  text "1" at 739.84,-1263.5 h70
  text "2" at 3235.5,-1263.5 h70
  text "3" at 5724.84,-1263.5 h70
  text "4" at 8231.51,-1263.5 h70
  text "5" at 10730.5,-1263.5 h70
  text "6" at 13235.5,-1263.5 h70
M10 Fab Notes:
  drawing of 189 lines, arcs and shapes, not listed
  text "DESIGN INFORMATION" at 12382.02,6356.17 h60
  text "MIN. TRACK WIDTH:" at 11737.46,6224.05 h60
  text "8" at 12833.7,6224.05 h60
  text "MIL" at 12988.46,6224.05 h60
  text "7.874" at 12667.32,6102.36 h60
  text "MIN. CLEARANCE:" at 11737.46,6099.92 h60
  text "MIL" at 12988.46,6099.92 h60
  text "MIN. VIA PAD SIZE:" at 11737.46,5975.8 h60
  text "24" at 12803.71,5975.8 h60
  text "MIL" at 12988.46,5975.8 h60
  text "0.05mm (2MIL)" at 12432.46,5845.9 h60
  text "MINIMUM ANNULAR RING" at 11408.23,5837.67 h60
  text "EXTERNAL" at 13140.46,5837.67 h60
  text "PER" at 11608.23,5727.55 h60
  text "IPC-D-275 CLASS 2 LEVEL C" at 11828.23,5727.54 h60
  text "MIL, HOLES" at 13316.46,5627.07 h60
  text "+/-" at 12924,5618.48 h60
  text "+/-" at 13778,5618.48 h60
  text "REGISTRATION TOLERANCES:" at 11408.23,5617.42 h60
  text "METAL" at 12608,5617.42 h60
  text "5" at 13184.2,5617.42 h60
  text "3" at 14017.2,5617.42 h60
  text "MIL" at 14133.46,5617.42 h60
  text "HOLE SIZE TOLERANCE (UNLESS OTHERWISE SPECIFIED):" at 11408.23,5519.1 h60
  text "+/-" at 13778,5516.23 h60
  text "3" at 14017.2,5515.17 h60
  text "MIL" at 14133.46,5515.17 h60
  text "MATERIAL:" at 11333.46,5377.52 h60
  text "FR-4 High Tg" at 12319.9,5249 h60
  text "X" at 12175.46,5241.01 h60
  text "FR-408" at 11754.46,5236.49 h60
  text "OTHER" at 13242.46,5236.49 h60
  text "62 MIL (1.6mm) +/-10%" at 12074.56,5093.46 h60
  text "X" at 11954.46,5091.01 h60
  text "THICKNESS:" at 11408.23,5085.24 h60
  text "OTHER" at 13359.46,5085.24 h60
  text "TOLERANCE:" at 11408.23,4946.92 h60
  text "X" at 12256.46,4946.92 h60
  text "ANSI IPC-6012 TYPE 3 CLASS 2" at 12434.48,4946.92 h60
  text "OTHER +/-" at 12434.46,4802.73 h60
  text "BOW & TWIST:" at 11408.23,4657.54 h60
  text "X" at 12256.46,4657.54 h60
  text "ANSI IPC-6012 TYPE 3 CLASS 2" at 12434.48,4657.54 h60
  text "OTHER +/-" at 12434.46,4510.85 h60
  text "DRILLING:" at 11333.46,4380.23 h60
  text "NC_DRILL FILES" at 13094.46,4275.04 h60
  text "REFERENCE:" at 11408.23,4271.1 h60
  text "X" at 12065.46,4271.01 h60
  text "AS SHOWN" at 12243.46,4271.1 h60
  text "X" at 12966.46,4271.1 h60
  text "OTHER" at 13392.46,4128.85 h60
  text "PTH COPPER THICKNESS:" at 11407.91,4125.32 h60
  text "X" at 12547.14,4125.32 h60
  text "20-30 um" at 12675.14,4125.32 h60
  text "BOARD FINISH:" at 11333.46,3977.73 h60
  text "SILKSCREEN:" at 11488.68,3867.6 h60
  text "X" at 12446.46,3867.6 h60
  text "TOP" at 12563.46,3867.6 h60
  text "X" at 12956.46,3867.6 h60
  text "BOTTOM" at 13074.46,3867.6 h60
  text "SILKSCREEN COLOR:" at 11488.68,3712.41 h60
  text "X" at 12445.46,3712.41 h60
  text "WHITE" at 12563.46,3712.41 h60
  text "OTHER" at 13074.46,3712.41 h60
  text "X" at 12576.46,3568.96 h60
  text "GREEN" at 12694.46,3568.96 h60
  text "OTHER" at 13312.46,3568.96 h60
  text "SOLDER RESIST COLOR:" at 11488.68,3562.1 h60
  text "X" at 12576.46,3414.71 h60
  text "MATTE" at 12694.46,3414.71 h60
  text "SEMI-GLOSS" at 13312,3414.07 h60
  text "IMMERSION GOLD (ENIG)" at 12394.46,3241.94 h60
  text "ENEPIG" at 13732,3234.72 h60
  text "SURFACE FINISH:" at 11333.46,3233.72 h60
  text "X" at 12216.46,3233.72 h60
  text "IMM. TIN/SILVER OR EQUIV" at 11663,3096.4 h60
  text "OTHER" at 13094.46,3092.47 h60
  text "ARRAY/PANEL:" at 11333.46,2937.09 h60
  text "CUT AND TRIM PER M1 BOARD OUTLINE" at 12394.46,2928.87 h60
  text "N.C. ROUTE" at 12394.46,2792.9 h60
  text "X" at 13082.46,2792.9 h60
  text "V. SCORE" at 13260.46,2792.9 h60
  text "CERTIFICATION:" at 11333.46,2663.77 h60
  text "MATERIALS AND WORKMANSHIP FOR ALL PCBS" at 12058.46,2663.77 h60
  text "TO MEET OR EXCEED THE REQUIREMENTS OF:" at 12058.46,2569.71 h60
  text "X" at 11695.97,2441.08 h60
  text "ANSI IPC-A-600F CLASS ->" at 11823.96,2441.08 h60
  text "X" at 13471.97,2441.08 h60
  text "2" at 13581.96,2441.08 h60
  text "1" at 13266.96,2439.58 h60
  text "3" at 13935.96,2439.58 h60
  text "X" at 12507.97,2293.39 h60
  text "RoHS" at 12635.96,2293.39 h60
  text "OTHER" at 13280.36,2293.39 h60
  text "PER ORDER" at 13677.42,2293.39 h60
  text "ALL BOARDS MUST MEET OR EXCEED UL94-V0 REQUIREMENTS." at 11361,2139.57 h60
  text "PCB MUST BEAR THE UL94V-0 UL REGISTERED MATERIAL ID NUMBER" at 11361,2023.5 h60
  text "ADDITIONAL REQUIREMENTS:" at 11333.46,1854.08 h60
  text "MICROSECTION:" at 11408.23,1746.95 h60
  text "YES" at 12313.96,1746.95 h60
  text "REQUIRED" at 13175.46,1602.62 h60
  text "BARE BOARD ELEC. TEST:" at 11408.23,1599.76 h60
  text "NONE" at 12713.96,1599.76 h60
  text "X" at 13057.46,1599.76 h60
  text "PER ORDER" at 13767.46,1599.76 h60
  text "XX MIL VIAS REQUIRE NON-CONDUCTIVE FILL AND PLANARIZE" at 11576.38,1394.82 h59
  text "XX MIL VIAS REQUIRE CONDUCTIVE FILL AND PLANARIZE" at 11584.38,1290.84 h60
  text "OUTER XX MIL TRACES REQUIRE 50 OHM SINGLE-ENDED IMPEDANCE" at 11583.39,1127.46 h58
  text "LAYER 2 & 3 (INNER LAYERS) XX MIL WIDE, XX MIL SPACE / TRACES REQUIRE 100 OHM DIFFERENTIAL IMPEDANCE" at 11575.39,891.74 h60
  text ".Layer_Name" at 577,-858.49 h60
M11 Gerber Information:
  lines w10: -292,-930.17 6308,-930.17 ; -292,-726.83 6310,-726.83 ; -292,-523.5 -292,-1133.5 3713,-1133.5 6310,-1133.5 6310,-523.5 -291.5,-523.5 -291.5,-1133.5 1284,-1133.5 ; 2173,-1133.5 2173,-523.5 ; 3440,-726.83 3440,-523.5 ; 4280,-726.83 4280,-523.5 ; 4902,-1140 4902,-937.17
  text "ALL ARTWORK VIEWED FROM TOP SIDE" at -228.5,-655.67 h60
  text "BOARD #:" at 2248,-655.67 h60
  text ".PRJ_Number" at 2793.5,-655.67 h60
  text "REV:" at 3638,-655.67 h60
  text ".PCB_Rev" at 3929.5,-655.67 h60
  text "SVN REV:" at 4476,-655.67 h60
  text ".VersionControl_RevNumber" at 4982,-655.67 h60
  text "LAYER NAME =" at -228.5,-858.49 h60
  text "TID #:" at 2248,-859 h60
  text ".TID" at 2793.5,-859 h60
  text "PLOT NAME =" at -228.5,-1064.34 h60
  text ".plot_File_Name" at 577,-1064.34 h60
  text "GENERATED    :" at 2250,-1064.34 h60
  text ".Print_Date" at 3119.5,-1064.34 h60
  text ".Print_Time" at 3848.5,-1064.34 h60
  text "TEXAS INSTRUMENTS" at 5113,-1064.34 h60
M12 Stackup:
  text ".Layer_Name" at 577,-858.49 h60
M13 Component Bodies Top:
  text ".Layer_Name" at 577,-858.49 h60
M14 Component Bodies Bottom:
  text ".Layer_Name" at 577,-858.49 h60
M15 Courtyards Top:
  text ".Layer_Name" at 577,-858.49 h60
M16 Courtyards Bottom:
  text ".Layer_Name" at 577,-858.49 h60
Drill Drawing:
  text ".Layer_Name" at 577,-858.49 h60
M17 Embedded Cavity:
  text ".Layer_Name" at 577,-858.49 h60
M18 Embedded Assembly:
  text ".Layer_Name" at 577,-858.49 h60
M19 Embedded Keepout:
  text ".Layer_Name" at 577,-858.49 h60

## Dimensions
0,-400 to 1000,-400 on M2 Board Dimensions
0,0 to 2732.07,0 on M2 Board Dimensions
0,0 to 0,1574.8 on M2 Board Dimensions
